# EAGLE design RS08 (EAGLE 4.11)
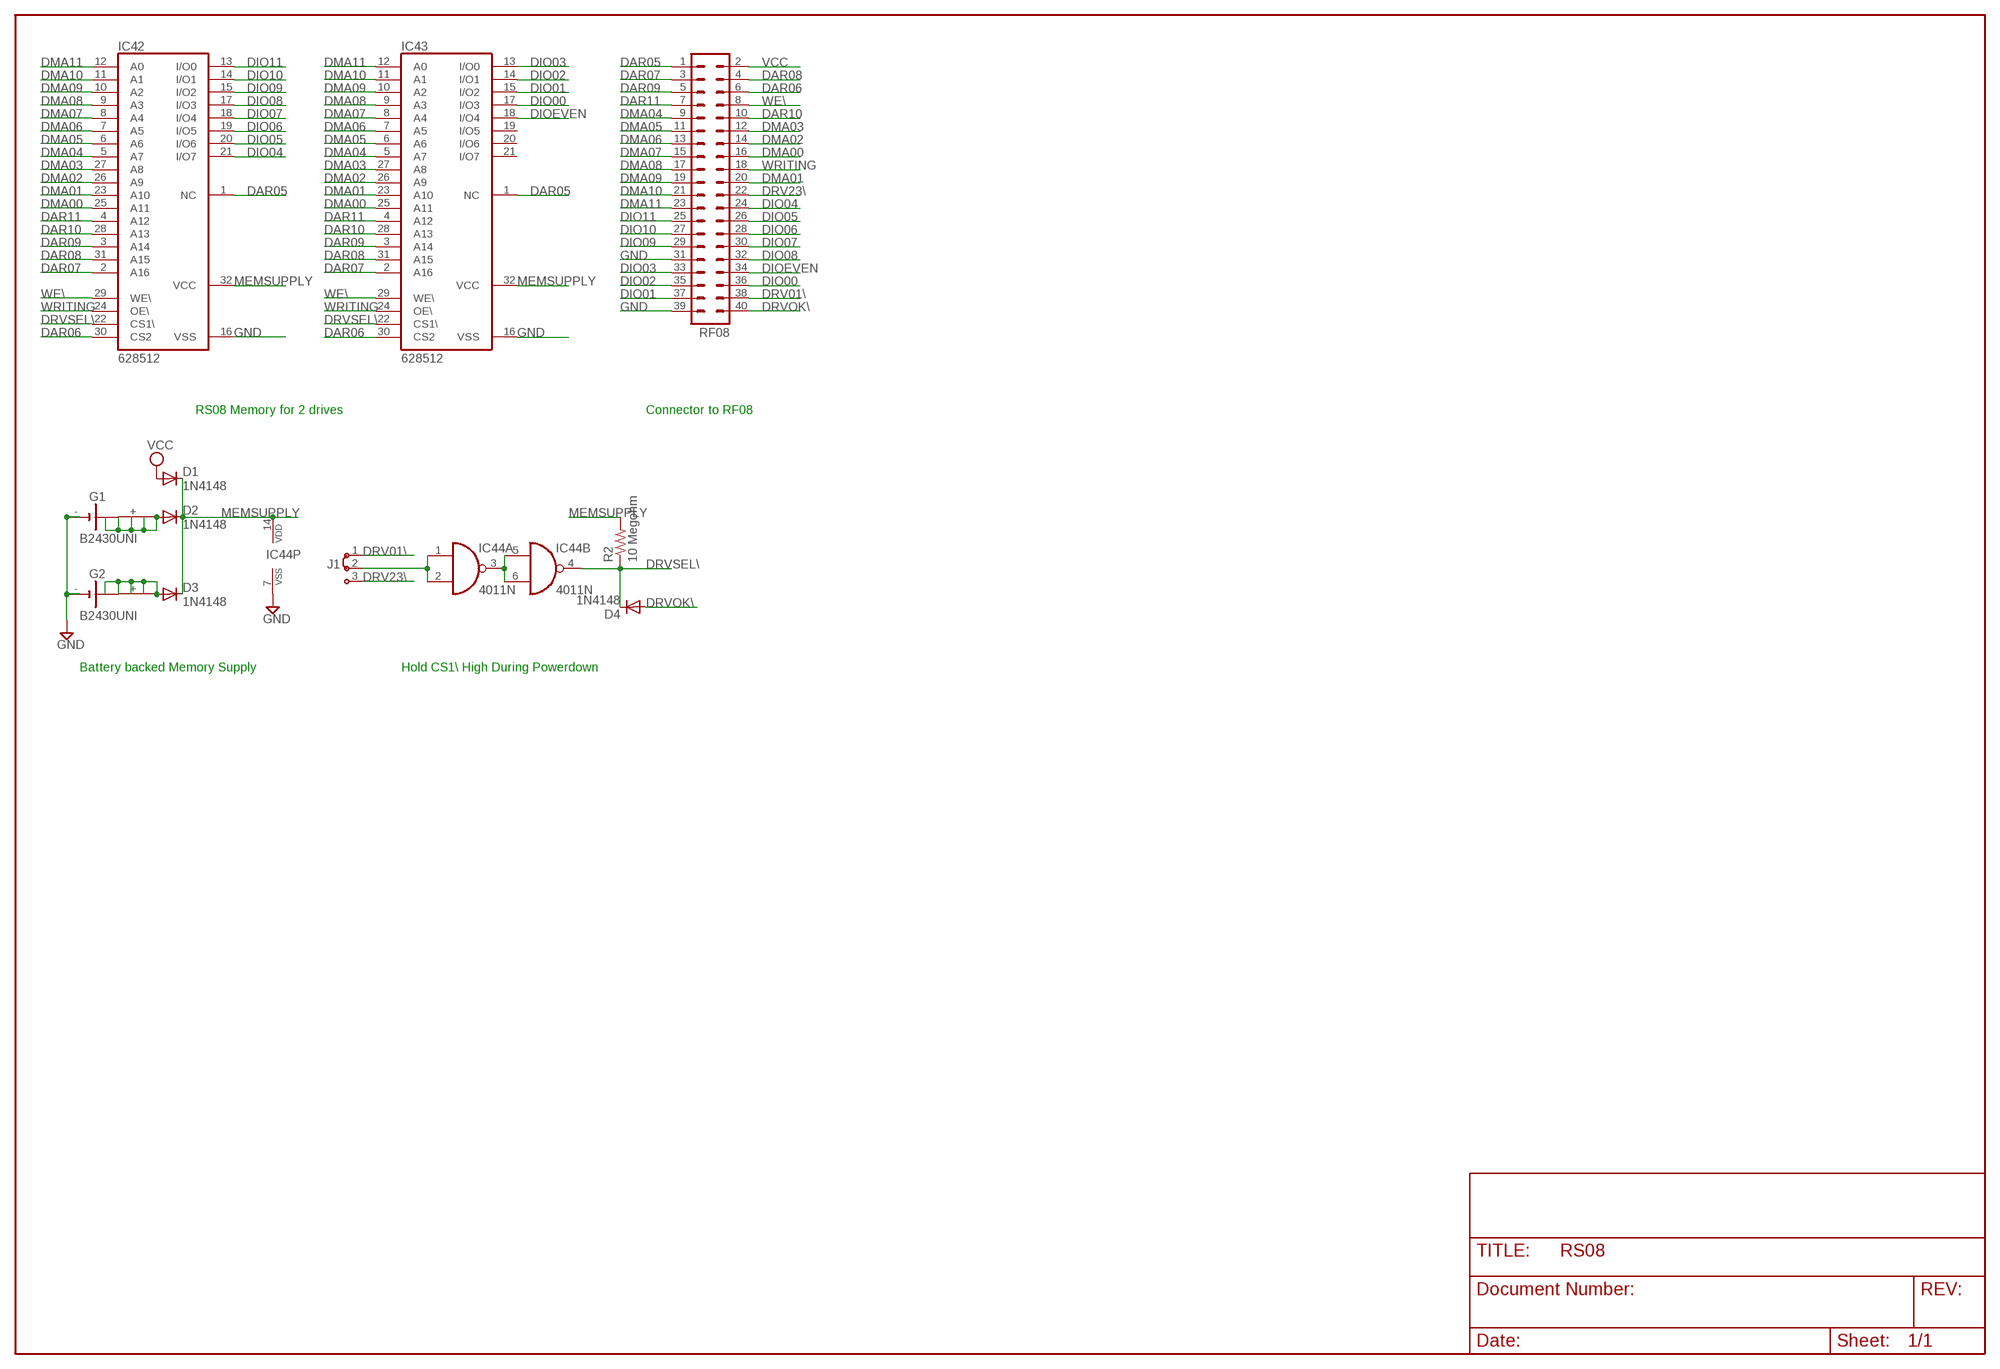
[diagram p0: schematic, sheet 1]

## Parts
D1  1N4148  [DO35-10]
D2  1N4148  [DO35-10]
D3  1N4148  [DO35-10]
D4  1N4148  [DO35-10]
G1  B2430UNI  [B2430UNI]
G2  B2430UNI  [B2430UNI]
IC42  628512  628128P  [DIL32]
IC43  628512  628128P  [DIL32]
IC44  4011N  [DIL14]
J1  J2X2MM  [04C]
R2  10 Megohm  R-US_0207/10  [0207/10]
RF08  MA20-2  [MA20-2]

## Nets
DAR05: IC42.1(NC) IC43.1(NC) RF08.1
DAR06: IC42.30(CS2) IC43.30(CS2) RF08.6
DAR07: IC42.2(A16) IC43.2(A16) RF08.3
DAR08: IC42.31(A15) IC43.31(A15) RF08.4
DAR09: IC42.3(A14) IC43.3(A14) RF08.5
DAR10: IC42.28(A13) IC43.28(A13) RF08.10
DAR11: IC42.4(A12) IC43.4(A12) RF08.7
DIO00: IC43.17(I/O3) RF08.36
DIO01: IC43.15(I/O2) RF08.37
DIO02: IC43.14(I/O1) RF08.35
DIO03: IC43.13(I/O0) RF08.33
DIO04: IC42.21(I/O7) RF08.24
DIO05: IC42.20(I/O6) RF08.26
DIO06: IC42.19(I/O5) RF08.28
DIO07: IC42.18(I/O4) RF08.30
DIO08: IC42.17(I/O3) RF08.32
DIO09: IC42.15(I/O2) RF08.29
DIO10: IC42.14(I/O1) RF08.27
DIO11: IC42.13(I/O0) RF08.25
DIOEVEN: IC43.18(I/O4) RF08.34
DMA00: IC42.25(A11) IC43.25(A11) RF08.16
DMA01: IC42.23(A10) IC43.23(A10) RF08.20
DMA02: IC42.26(A9) IC43.26(A9) RF08.14
DMA03: IC42.27(A8) IC43.27(A8) RF08.12
DMA04: IC42.5(A7) IC43.5(A7) RF08.9
DMA05: IC42.6(A6) IC43.6(A6) RF08.11
DMA06: IC42.7(A5) IC43.7(A5) RF08.13
DMA07: IC42.8(A4) IC43.8(A4) RF08.15
DMA08: IC42.9(A3) IC43.9(A3) RF08.17
DMA09: IC42.10(A2) IC43.10(A2) RF08.19
DMA10: IC42.11(A1) IC43.11(A1) RF08.21
DMA11: IC42.12(A0) IC43.12(A0) RF08.23
DRV01\: J1.1 RF08.38
DRV23\: J1.3 RF08.22
DRVOK\: D4.A RF08.40
DRVSEL\: D4.C IC42.22(CS1\) IC43.22(CS1\) IC44.4(B:O) R2.1
GND [Power]: G1.- G1.-@1(-) G2.- G2.-@1(-) IC42.16(VSS) IC43.16(VSS) IC44.7(P:VSS) RF08.31 RF08.39
MEMSUPPLY [Power]: D1.C D2.C D3.C IC42.32(VCC) IC43.32(VCC) IC44.14(P:VDD) R2.2
N$18: IC44.3(A:O) IC44.5(B:I0) IC44.6(B:I1)
N$35: IC44.1(A:I0) IC44.2(A:I1) J1.2
N$130: D3.A G2.+ G2.+@1(+) G2.+@2(+) G2.+@3(+) G2.+@4(+)
N$131: D2.A G1.+ G1.+@1(+) G1.+@2(+) G1.+@3(+) G1.+@4(+)
VCC [Power]: D1.A RF08.2
WE\: IC42.29(WE\) IC43.29(WE\) RF08.8
WRITING: IC42.24(OE\) IC43.24(OE\) RF08.18
Unconnected: IC43.19(I/O5) IC43.20(I/O6) IC43.21(I/O7) IC44.8(C:I0) IC44.9(C:I1) IC44.10(C:O) IC44.11(D:O) IC44.12(D:I0) IC44.13(D:I1)

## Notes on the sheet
- RS08 Memory for 2 drives | Connector to RF08
- Battery backed Memory Supply | Hold CS1\ High During Powerdown

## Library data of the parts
D1-D4 = diode:1N4148: DIODE
G1 G2 = battery:B2430UNI: LI BATTERY
IC42 IC43 = memory-hitachi:628128P: MEMORY
IC44 = 40xx:4011: Quad 2-input NAND
J1 = jumper:J2: Jumper switch 2 x 2.5 mm
R2 = rcl:R-US_: RESISTOR, American symbol
RF08 = con-lstb:MA20-2: PIN HEADER

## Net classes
1 Power: width 0.508 mm

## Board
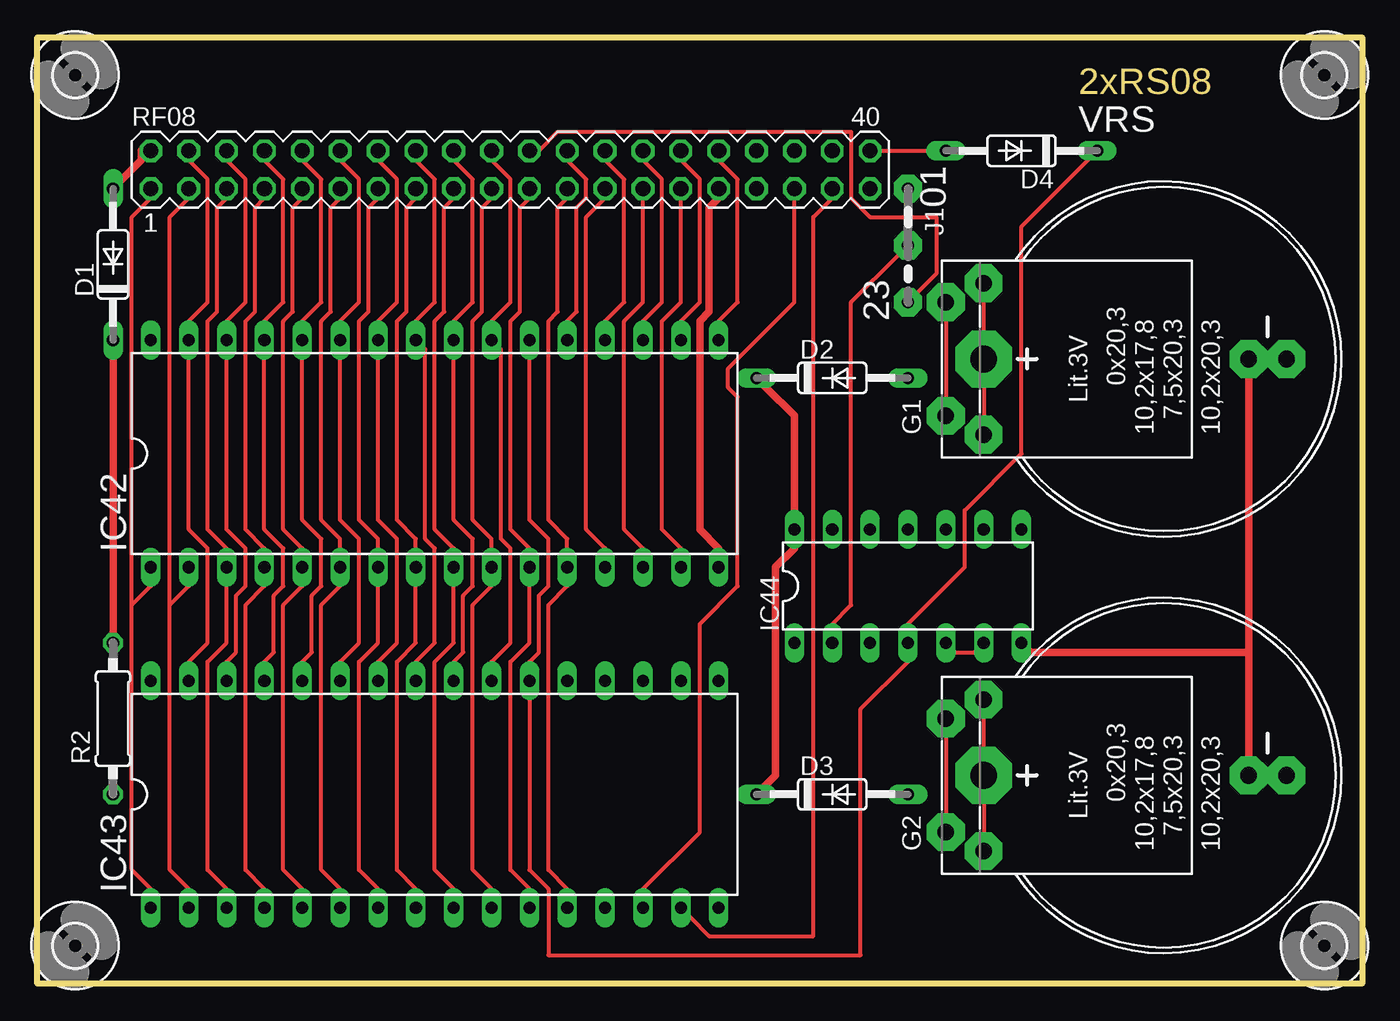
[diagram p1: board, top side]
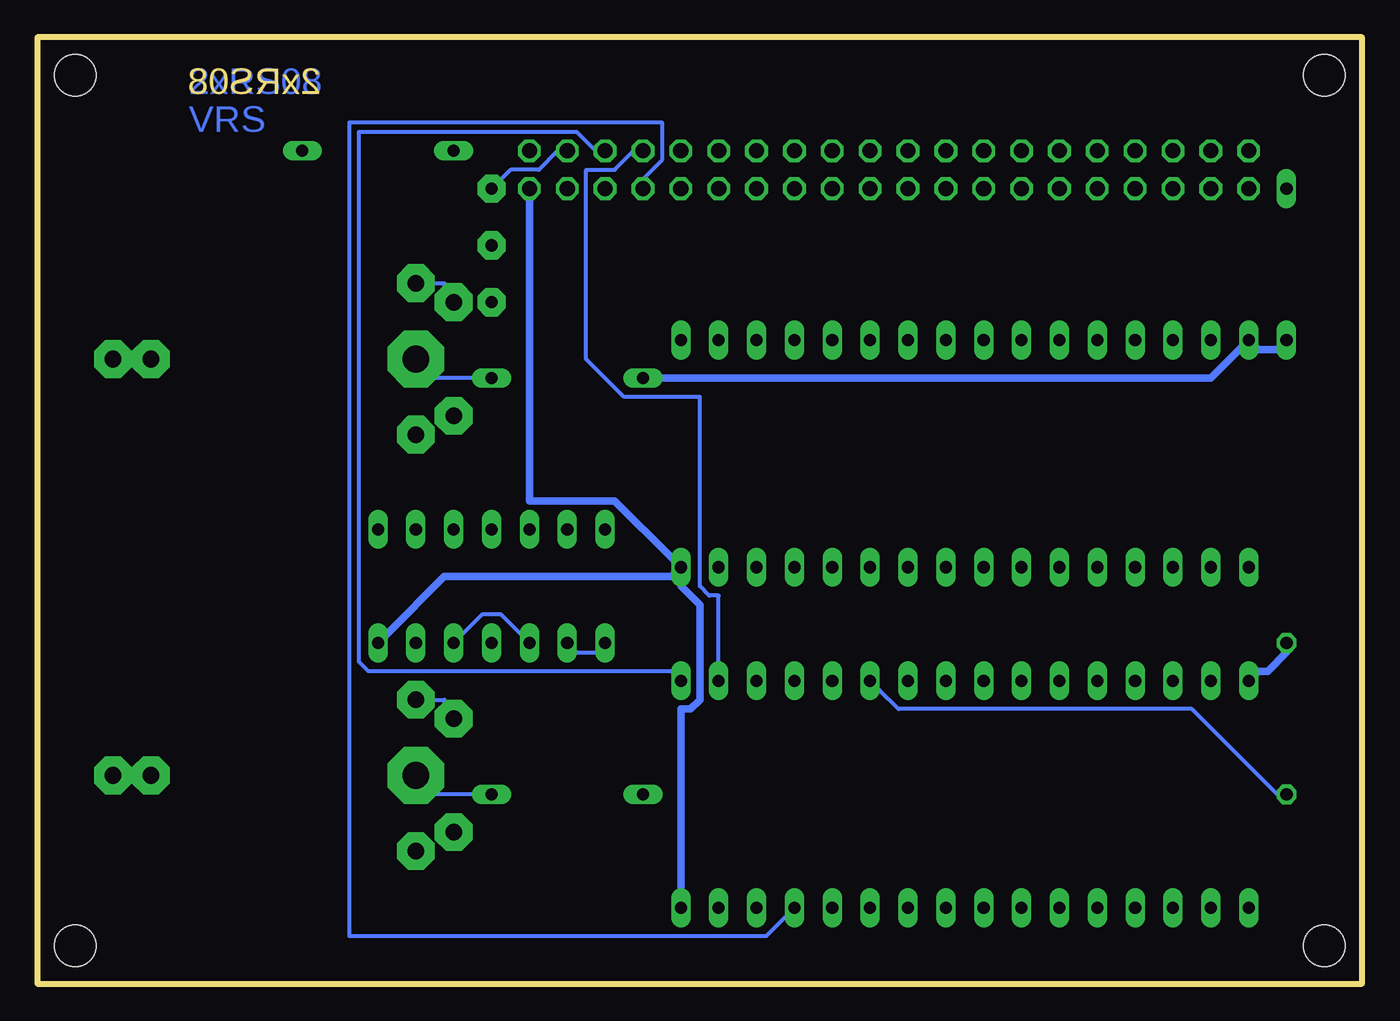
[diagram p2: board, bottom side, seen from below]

Size 88.9 x 63.5 mm. Coordinates in mm from the lower left corner, seen from the top.
Outline: 0,63.5 88.9,63.5 88.9,0 0,0 0,63.5
Copper layers (1*16): Top 0.035mm / dielectric 1.5mm / Bottom 0.035mm
Design rules "default": minimum track width 10mil, minimum drill 24mil, track to track 8mil, track to pad 8mil, pad to pad 8mil, via to via 8mil, smd to smd 8mil, copper to edge 40mil, drill to drill 8mil, minimum pad ring 10mil, minimum via ring 8mil, stop-mask expansion 4mil, vias tented up to drill 0mil, thermal gap 10mil

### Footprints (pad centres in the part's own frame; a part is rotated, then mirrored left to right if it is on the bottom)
DO35-10 = drill 0.813 long: A 5.08,0; C -5.08,0
B2430UNI = drill 1.118 pad 2.54 octagon: + 3.81,14.605; +@1 -3.81,14.605; +@2 -5.08,12.065; +@3 5.08,12.065; - 0,-5.715; -@1 0,-8.255 | drill 1.803 pad 3.81 octagon: +@4 0,12.065
DIL32 = drill 0.813 long: 1 -19.05,-7.62; 2 -16.51,-7.62; 3 -13.97,-7.62; 4 -11.43,-7.62; 5 -8.89,-7.62; 6 -6.35,-7.62; 7 -3.81,-7.62; 8 -1.27,-7.62; 9 1.27,-7.62; 10 3.81,-7.62; 11 6.35,-7.62; 12 8.89,-7.62; 13 11.43,-7.62; 14 13.97,-7.62; 15 16.51,-7.62; 16 19.05,-7.62; 17 19.05,7.62; 18 16.51,7.62; 19 13.97,7.62; 20 11.43,7.62; 21 8.89,7.62; 22 6.35,7.62; 23 3.81,7.62; 24 1.27,7.62; 25 -1.27,7.62; 26 -3.81,7.62; 27 -6.35,7.62; 28 -8.89,7.62; 29 -11.43,7.62; 30 -13.97,7.62; 31 -16.51,7.62; 32 -19.05,7.62
DIL14 = drill 0.813 long: 1 -7.62,-3.81; 2 -5.08,-3.81; 3 -2.54,-3.81; 4 0,-3.81; 5 2.54,-3.81; 6 5.08,-3.81; 7 7.62,-3.81; 8 7.62,3.81; 9 5.08,3.81; 10 2.54,3.81; 11 0,3.81; 12 -2.54,3.81; 13 -5.08,3.81; 14 -7.62,3.81
04C = drill 0.813 pad 1.905 octagon: 1 -1.905,0; 2 1.905,0; 3 5.715,0
0207/10 = drill 0.813 octagon: 1 -5.08,0; 2 5.08,0
MA20-2 = drill 1.016 octagon: 1 -24.13,-1.27; 2 -24.13,1.27; 3 -21.59,-1.27; 4 -21.59,1.27; 5 -19.05,-1.27; 6 -19.05,1.27; 7 -16.51,-1.27; 8 -16.51,1.27; 9 -13.97,-1.27; 10 -13.97,1.27; 11 -11.43,-1.27; 12 -11.43,1.27; 13 -8.89,-1.27; 14 -8.89,1.27; 15 -6.35,-1.27; 16 -6.35,1.27; 17 -3.81,-1.27; 18 -3.81,1.27; 19 -1.27,-1.27; 20 -1.27,1.27; 21 1.27,-1.27; 22 1.27,1.27; 23 3.81,-1.27; 24 3.81,1.27; 25 6.35,-1.27; 26 6.35,1.27; 27 8.89,-1.27; 28 8.89,1.27; 29 11.43,-1.27; 30 11.43,1.27; 31 13.97,-1.27; 32 13.97,1.27; 33 16.51,-1.27; 34 16.51,1.27; 35 19.05,-1.27; 36 19.05,1.27; 37 21.59,-1.27; 38 21.59,1.27; 39 24.13,-1.27; 40 24.13,1.27
2,8 = hole 2.8: 0,0

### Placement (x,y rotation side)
D1  5.08,48.26 90 top
D2  53.34,40.64 0 top
D3  53.34,12.7 0 top
D4  66.04,55.88 180 top
G1  75.56,41.91 90 top
G2  75.56,13.97 90 top
IC42  26.67,35.56 0 top
IC43  26.67,12.7 0 top
IC44  58.42,26.67 0 top
J1  58.42,51.44 270 top
R2  5.08,17.78 90 top
RF08  31.75,54.61 0 top
U$5  [2,8]  86.36,2.54 0 top
U$6  [2,8]  2.54,2.54 0 top
U$7  [2,8]  2.54,60.96 0 top
U$8  [2,8]  86.36,60.96 0 top

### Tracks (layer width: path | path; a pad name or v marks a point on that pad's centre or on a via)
DAR05
  Top 0.254: 6.35,25.4 6.35,7.62 7.62,6.35 IC43.1 | 6.35,25.4 7.62,26.67 IC42.1 | 6.35,25.4 6.35,51.44 7.62,52.7 RF08.1
DAR06
  Top 0.254: IC43.30 12.7,21.59 13.34,22.23 13.34,26.04 13.97,26.67 13.97,29.21 12.7,30.48 12.7,41.91 IC42.30 12.7,44.45 13.97,45.72 13.97,53.98 12.7,55.24 RF08.6
DAR07
  Top 0.254: 8.89,25.4 8.89,7.62 10.16,6.35 IC43.2 | 8.89,25.4 10.16,26.67 IC42.2 | 8.89,25.4 8.89,51.44 10.16,52.7 RF08.3
DAR08
  Top 0.254: IC43.31 10.16,21.59 11.43,22.86 11.43,29.21 10.16,30.48 10.16,41.91 IC42.31 10.16,44.45 11.43,45.72 11.43,53.98 10.16,55.24 RF08.4
DAR09
  Top 0.254: IC43.3 12.7,6.35 11.43,7.62 11.43,21.59 12.7,22.86 12.7,26.67 IC42.3 12.7,29.21 11.43,30.48 11.43,44.45 12.06,45.09 12.06,52.07 12.7,52.7 RF08.5
DAR10
  Top 0.254: IC43.28 17.78,21.59 18.41,22.23 18.41,26.04 19.05,26.67 19.05,29.84 17.78,31.11 17.78,41.91 IC42.28 17.78,44.45 19.05,45.72 19.05,53.98 17.78,55.24 RF08.10
DAR11
  Top 0.254: IC43.4 15.24,6.35 13.97,7.62 13.97,25.4 15.24,26.67 IC42.4 15.24,29.21 13.97,30.48 13.97,44.45 14.61,45.09 14.61,52.07 15.24,52.7 RF08.7
DIO00
  Bottom 0.254: IC43.17 46.35,20.95 66.67,20.95 67.31,21.59 67.31,57.15 52.7,57.15 51.44,55.88 RF08.36
DIO01
  Top 0.254: IC43.15 43.81,4.45 45.09,3.17 52.07,3.17 52.07,51.44 53.34,52.7 RF08.37
DIO02
  Top 0.254: IC43.14 40.64,6.35 44.45,10.16 44.45,24.13 46.99,26.67 46.99,39.37 46.35,40.01 46.35,41.27 50.8,45.72 50.8,52.7 RF08.35
DIO03
  Bottom 0.254: RF08.33 48.26,53.98 46.99,55.24 46.99,57.78 67.94,57.78 67.94,3.17 40.01,3.17 38.73,4.45 IC43.13
DIO04
  Top 0.254: IC42.21 35.56,44.45 36.2,45.09 36.2,52.07 36.83,52.7 36.83,53.98 35.56,55.24 RF08.24
DIO05
  Top 0.254: IC42.20 38.1,44.45 39.37,45.72 39.37,53.98 38.1,55.24 RF08.26
DIO06
  Top 0.254: IC42.19 40.64,44.45 41.91,45.72 41.91,53.98 40.64,55.24 RF08.28
DIO07
  Top 0.254: IC42.18 43.18,44.45 44.45,45.72 44.45,53.98 43.18,55.24 RF08.30
DIO08
  Top 0.254: IC42.17 45.72,44.45 46.99,45.72 46.99,53.98 45.72,55.24 RF08.32
DIO09
  Top 0.254: IC42.15 43.18,29.21 41.91,30.48 41.91,44.45 43.18,45.72 43.18,52.7 RF08.29
DIO10
  Top 0.254: IC42.14 40.64,29.21 39.37,30.48 39.37,44.45 40.64,45.72 40.64,52.7 RF08.27
DIO11
  Top 0.254: IC42.13 38.1,29.21 36.83,30.48 36.83,51.44 38.1,52.7 RF08.25
DIOEVEN
  Bottom 0.254: IC43.18 43.18,21.59 43.18,26.04 43.81,26.04 44.45,26.67 44.45,39.37 49.53,39.37 52.07,41.91 52.07,54.61 50.16,54.61 48.9,55.88 RF08.34
DMA00
  Top 0.254: IC43.25 25.4,21.59 26.67,22.86 26.67,29.21 26.04,29.84 26.04,42.55 IC42.25 25.4,44.45 26.67,45.72 26.67,53.98 25.4,55.24 RF08.16
DMA01
  Top 0.254: IC43.23 30.48,21.59 31.75,22.86 31.75,29.21 31.11,29.84 31.11,42.55 IC42.23 30.48,44.45 31.75,45.72 31.75,53.98 30.48,55.24 RF08.20
DMA02
  Top 0.254: IC43.26 22.86,21.59 24.13,22.86 24.13,29.84 22.86,31.11 22.86,41.91 IC42.26 22.86,44.45 24.13,45.72 24.13,53.98 22.86,55.24 RF08.14
DMA03
  Top 0.254: IC43.27 20.32,21.59 21.59,22.86 21.59,29.84 20.32,31.11 20.32,41.91 IC42.27 20.32,44.45 21.59,45.72 21.59,53.98 20.32,55.24 RF08.12
DMA04
  Top 0.254: IC43.5 17.78,6.35 16.51,7.62 16.51,25.4 17.78,26.67 IC42.5 17.78,29.21 16.51,30.48 16.51,44.45 17.14,45.09 17.14,52.07 17.78,52.7 RF08.9
DMA05
  Top 0.254: IC43.6 20.32,6.35 19.05,7.62 19.05,25.4 20.32,26.67 IC42.6 20.32,29.21 20.32,29.84 19.05,31.11 19.05,44.45 19.68,45.09 19.68,52.07 20.32,52.7 RF08.11
DMA06
  Top 0.254: IC43.7 22.86,6.35 21.59,7.62 21.59,21.59 22.86,22.86 22.86,26.67 IC42.7 22.86,29.21 22.86,29.84 21.59,31.11 21.59,44.45 22.23,45.09 22.23,52.07 22.86,52.7 RF08.13
DMA07
  Top 0.254: IC43.8 25.4,6.35 24.13,7.62 24.13,21.59 25.4,22.86 25.4,26.67 IC42.8 25.4,29.21 25.4,29.84 24.13,31.11 24.13,44.45 24.77,45.09 24.77,52.07 25.4,52.7 RF08.15
DMA08
  Top 0.254: IC43.9 27.94,6.35 26.67,7.62 26.67,21.59 27.94,22.86 27.94,26.67 IC42.9 27.94,29.21 26.67,30.48 26.67,44.45 27.3,45.09 27.3,52.07 27.94,52.7 RF08.17
DMA09
  Top 0.254: IC43.10 30.48,6.35 29.21,7.62 29.21,25.4 30.48,26.67 IC42.10 30.48,29.21 30.48,29.84 29.21,31.11 29.21,44.45 29.84,45.09 29.84,52.07 30.48,52.7 RF08.19
DMA10
  Top 0.254: IC43.11 33.02,6.35 31.75,7.62 31.75,21.59 33.02,22.86 33.02,26.67 IC42.11 33.02,29.21 31.75,30.48 31.75,44.45 32.38,45.09 32.38,52.07 33.02,52.7 RF08.21
DMA11
  Top 0.254: IC43.12 35.56,6.35 34.29,7.62 34.29,25.4 35.56,26.67 IC42.12 35.56,29.21 35.56,29.84 34.29,31.11 34.29,44.45 34.92,45.09 34.92,52.07 35.56,52.7 RF08.23
DRV01\
  Bottom 0.254: RF08.38 53.98,55.88 55.24,54.61 57.15,54.61 57.78,53.98 J1.1
DRV23\
  Top 0.254: RF08.22 33.66,55.88 34.92,57.15 54.61,57.15 54.61,52.7 55.88,51.44 60.33,51.44 60.33,47.62 59.05,46.35 J1.3
DRVOK\
  Top 0.254: D4.A 59.69,55.88 56.52,55.88 RF08.40
DRVSEL\
  Top 0.254: IC42.22 33.02,41.91 33.02,31.11 34.29,29.84 34.29,26.67 33.66,26.04 33.66,22.23 33.02,21.59 IC43.22 33.02,19.05 33.02,7.62 34.29,6.35 34.29,1.91 55.24,1.91 55.24,18.41 58.42,21.59 IC44.4 58.42,24.13 62.23,27.94 62.23,31.75 66.04,35.56 66.04,50.8 70.48,55.24 D4.C
  Bottom 0.254: R2.1 5.71,12.7 11.43,18.41 31.11,18.41 32.38,19.68 IC43.22
GND
  Top 0.508: 81.28,22.23 81.28,14.61 G2.- | 81.28,22.23 81.28,41.27 G1.- | 81.28,22.23 66.67,22.23 IC44.7 | RF08.31 45.72,52.7 45.09,52.07 45.09,45.09 44.45,44.45 44.45,30.48 45.72,29.21 IC42.16
  Bottom 0.508: G2.- 81.92,13.97 83.19,13.97 G2.-@1 | G1.- 81.92,41.91 83.19,41.91 G1.-@1 | IC44.7 65.41,23.5 61.59,27.3 46.35,27.3 IC42.16 | IC43.16 45.72,6.35 45.72,18.41 45.09,18.41 44.45,19.05 44.45,25.4 45.72,26.67 IC42.16 | RF08.39 55.88,52.7 55.88,32.38 50.16,32.38 46.35,28.57 IC42.16
MEMSUPPLY
  Top 0.508: D1.C 5.08,41.91 5.08,23.5 R2.2 | D3.C 48.9,13.34 49.53,13.97 49.53,27.94 50.8,29.21 IC44.14 50.8,31.75 50.8,38.1 48.9,40.01 D2.C
  Bottom 0.508: D1.C 5.71,42.55 6.99,42.55 IC42.32 8.26,42.55 10.16,40.64 46.99,40.64 D2.C | R2.2 5.08,22.23 6.35,20.95 6.99,20.95 IC43.32
N$18
  Top 0.254: IC44.6 62.87,22.23 61.59,22.23 IC44.5
  Bottom 0.254: IC44.3 56.52,23.5 57.78,24.77 59.05,24.77 60.33,23.5 IC44.5
N$35
  Top 0.254: IC44.2 53.34,24.13 54.61,25.4 54.61,45.72 57.78,48.9 J1.2
  Bottom 0.254: IC44.1 51.44,22.23 52.7,22.23 IC44.2
N$130
  Top 0.254: G2.+ 60.96,17.14 60.96,10.79 G2.+@1 | G2.+@2 63.5,9.53 63.5,12.7 G2.+@4 63.5,15.24 63.5,18.41 G2.+@3
  Bottom 0.254: D3.A 59.69,12.7 62.23,12.7 G2.+@4 | G2.+ 61.59,18.41 61.59,19.05 62.87,19.05 G2.+@3
N$131
  Top 0.254: G1.+ 60.96,45.09 60.96,38.73 G1.+@1 | G1.+@2 63.5,37.47 63.5,40.64 G1.+@4 63.5,43.18 63.5,46.35 G1.+@3
  Bottom 0.254: D2.A 59.69,40.64 62.23,40.64 G1.+@4 | G1.+ 61.59,46.35 61.59,46.99 62.87,46.99 G1.+@3
VCC
  Top 0.508: D1.A 5.71,53.98 6.99,55.24 6.99,55.88 RF08.2
WE\
  Top 0.254: IC43.29 15.24,21.59 15.88,22.23 15.88,26.04 16.51,26.67 16.51,29.21 15.24,30.48 15.24,41.91 IC42.29 15.24,44.45 16.51,45.72 16.51,53.98 15.24,55.24 RF08.8
WRITING
  Top 0.254: IC43.24 27.94,21.59 28.57,22.23 28.57,26.04 29.21,26.67 29.21,29.84 27.94,31.11 27.94,41.91 IC42.24 27.94,44.45 29.21,45.72 29.21,53.98 27.94,55.24 RF08.18

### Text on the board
Bottom: 2xRS08 | VRS
Dimension: 2xRS08
tPlace: VRS | 01 | 23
